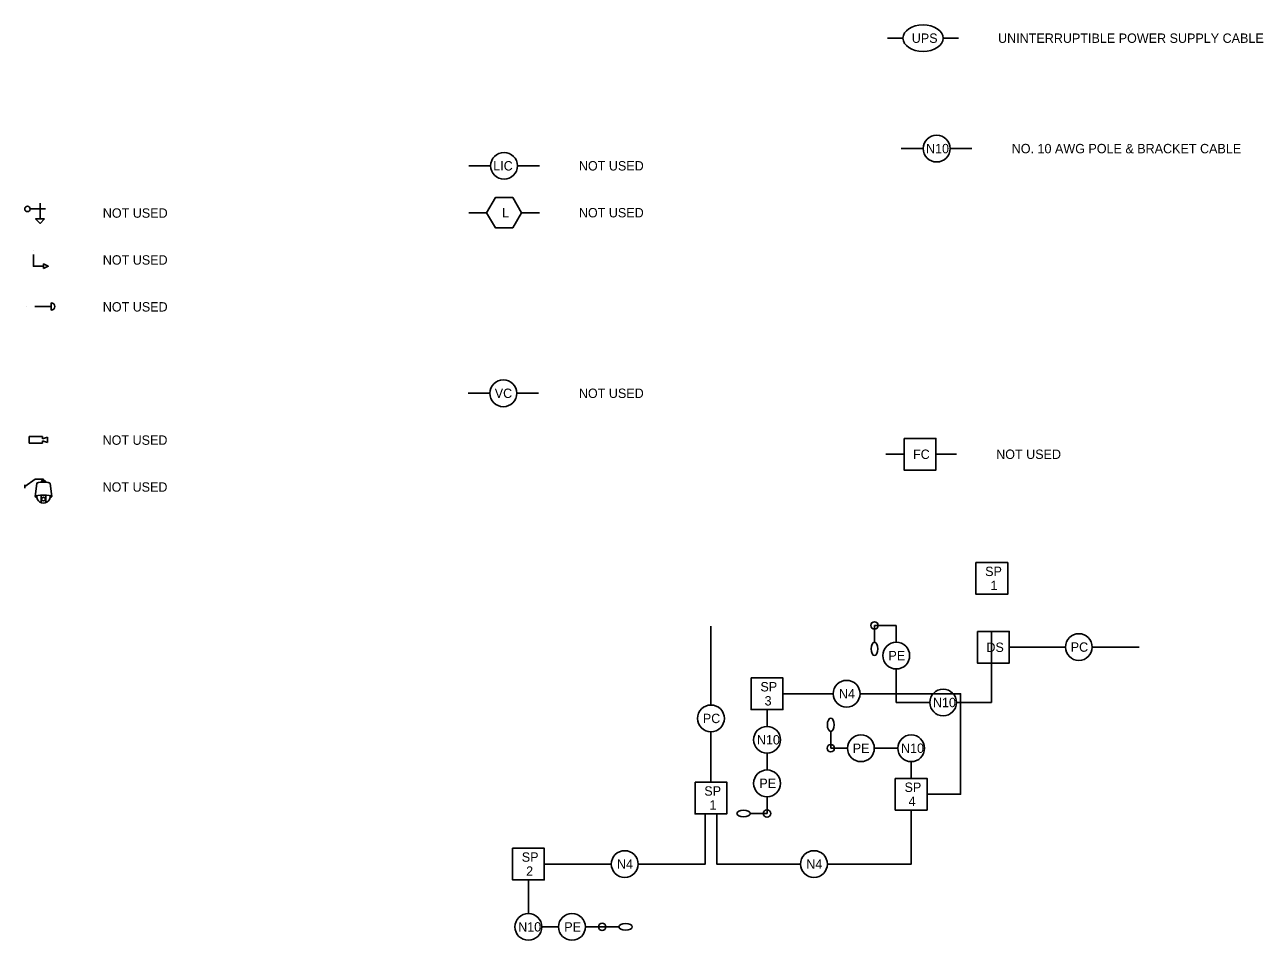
# Model space of a CAD drawing. Extents: x 32.6 to 95.8, y 11.4 to 49.5.
# Drawn here: x 55.45 to 73.93, y 11.38 to 25.04 of the extents above; entities that cross this region are included whole.
import ezdxf

# ---------------------------------------------------------------- set-up
doc = ezdxf.new("R2010")
doc.units = 0
for name, color, linetype in [('LT_P_Luminaires', 7, 'Continuous'), ('SG_P_Detection', 7, 'Continuous'), ('SG_P_Heads', 7, 'Continuous'), ('SG_P_Text', 7, 'Continuous'), ('SH_Data', 7, 'Continuous'), ('SH_Text', 7, 'Continuous')]:
    doc.layers.add(name, color=color, linetype=linetype)

msp = doc.modelspace()

# ---------------------------------------------------------------- linework, layer by layer
at = {"layer": 'LT_P_Luminaires'}
for p, q in [((68.129, 16.078), (68.129, 15.828)), ((67.477, 14.245), (67.477, 14.495)), ((66.527, 13.271), (66.277, 13.271)), ((64.067, 11.579), (64.317, 11.579))]:
    msp.add_line(p, q, dxfattribs=at)
for centre in [(68.129, 16.078), (67.477, 14.245), (66.527, 13.271), (64.067, 11.579)]:
    msp.add_circle(centre, 0.055, dxfattribs=at)
for centre, major_axis in [((68.129, 15.728), (0, -0.1)), ((67.477, 14.595), (0, 0.1)), ((66.177, 13.271), (-0.1, 0)), ((64.417, 11.579), (0.1, 0))]:
    msp.add_ellipse(centre, major_axis=major_axis, ratio=0.5, dxfattribs=at)
at = {"layer": 'SG_P_Detection'}
for p, q in [((55.846, 20.894), (55.846, 20.782)), ((55.486, 20.838), (55.486, 20.838)), ((55.606, 20.838), (55.846, 20.838)), ((55.52, 18.9), (55.72, 18.9)), ((55.52, 18.8), (55.52, 18.9)), ((55.72, 18.9), (55.72, 18.865)), ((55.72, 18.865), (55.795, 18.89)), ((55.795, 18.89), (55.795, 18.81)), ((55.72, 18.8), (55.52, 18.8)), ((55.795, 18.81), (55.72, 18.835)), ((55.72, 18.835), (55.72, 18.8)), ((55.454, 18.125), (55.454, 18.175)), ((55.632, 18.198), (55.607, 18.002)), ((55.732, 18.262), (55.732, 18.237)), ((55.832, 18.198), (55.857, 18.002)), ((55.697, 18.022), (55.697, 17.909)), ((55.767, 18.022), (55.767, 17.909))]:
    msp.add_line(p, q, dxfattribs=at)
for points in [[(55.732, 18.262), (55.607, 18.262), (55.454, 18.15)], [(55.707, 18.217), (55.707, 18.237), (55.757, 18.237), (55.757, 18.217)]]:
    msp.add_lwpolyline(points, dxfattribs=at)
msp.add_circle((55.732, 17.964), 0.0273, dxfattribs=at)
for centre, radius, start, end in [((55.846, 20.838), 0.056, 270.0002, 89.9998), ((55.732, 18.002), 0.1, 173.0175, 6.9825)]:
    msp.add_arc(centre, radius, start, end, dxfattribs=at)
for centre, major_axis, ratio, start_param, end_param in [((55.732, 18.198), (0.1, 0), 0.2, 0, 3.141593), ((55.732, 18.002), (0.125, 0), 0.16, 5.62986, 10.078104)]:
    msp.add_ellipse(centre, major_axis=major_axis, ratio=ratio, start_param=start_param, end_param=end_param, dxfattribs=at)
at = {"layer": 'SG_P_Heads'}
for p, q in [((55.683, 22.38), (55.683, 22.145)), ((55.534, 22.294), (55.764, 22.294)), ((55.584, 21.673), (55.584, 21.673))]:
    msp.add_line(p, q, dxfattribs=at)
for points in [[(55.75, 22.145), (55.683, 22.078), (55.616, 22.145)], [(55.734, 21.403), (55.734, 21.473), (55.804, 21.438)]]:
    msp.add_lwpolyline(points, close=True, dxfattribs=at)
msp.add_lwpolyline([(55.584, 21.613), (55.584, 21.438), (55.734, 21.438)], dxfattribs=at)
msp.add_circle((55.494, 22.294), 0.04, dxfattribs=at)
at = {"layer": 'SG_P_Text'}
for p, q in [((68.554, 24.843), (68.326, 24.843)), ((69.381, 24.843), (69.154, 24.843)), ((68.857, 23.195), (68.53, 23.195)), ((69.584, 23.195), (69.257, 23.195)), ((62.404, 22.938), (62.077, 22.938)), ((63.131, 22.938), (62.804, 22.938)), ((62.344, 22.238), (62.077, 22.238)), ((63.131, 22.238), (62.864, 22.238)), ((62.393, 19.543), (62.066, 19.543)), ((63.12, 19.543), (62.793, 19.543)), ((68.572, 18.633), (68.298, 18.633)), ((69.352, 18.633), (69.046, 18.633))]:
    msp.add_line(p, q, dxfattribs=at)
for points in [[(62.864, 22.238), (62.734, 22.463), (62.474, 22.463), (62.344, 22.238), (62.474, 22.013), (62.734, 22.013)], [(68.572, 18.87), (69.046, 18.87), (69.046, 18.396), (68.572, 18.396)], [(69.644, 17.017), (70.117, 17.017), (70.117, 16.543), (69.644, 16.543)], [(69.666, 15.989), (70.14, 15.989), (70.14, 15.515), (69.666, 15.515)], [(66.29, 15.295), (66.764, 15.295), (66.764, 14.821), (66.29, 14.821)], [(65.454, 13.74), (65.927, 13.74), (65.927, 13.266), (65.454, 13.266)], [(68.44, 13.795), (68.914, 13.795), (68.914, 13.321), (68.44, 13.321)], [(62.73, 12.753), (63.204, 12.753), (63.204, 12.279), (62.73, 12.279)]]:
    msp.add_lwpolyline(points, close=True, dxfattribs=at)
for centre in [(69.057, 23.195), (62.604, 22.938), (62.593, 19.543), (71.178, 15.755), (68.454, 15.628), (67.714, 15.058), (69.154, 14.928), (65.69, 14.69), (66.527, 14.371), (67.927, 14.245), (68.677, 14.245), (66.527, 13.721), (64.404, 12.516), (67.227, 12.516), (62.967, 11.579), (63.617, 11.579)]:
    msp.add_circle(centre, 0.2, dxfattribs=at)
msp.add_ellipse((68.854, 24.843), major_axis=(0.3, 0), ratio=0.666667, dxfattribs=at)
at = {"layer": 'SH_Data'}
for p, q in [((68.129, 16.078), (68.454, 16.078)), ((68.454, 15.828), (68.454, 16.078)), ((65.69, 16.066), (65.69, 14.89)), ((69.876, 15.992), (69.876, 14.928)), ((70.978, 15.755), (70.14, 15.755)), ((72.078, 15.755), (71.378, 15.755)), ((68.454, 14.928), (68.454, 15.428)), ((67.514, 15.058), (66.764, 15.058)), ((66.527, 14.821), (66.527, 14.571)), ((68.954, 14.928), (68.454, 14.928)), ((69.876, 14.928), (69.354, 14.928)), ((65.69, 14.49), (65.69, 13.74)), ((67.727, 14.245), (67.477, 14.245)), ((68.477, 14.245), (68.127, 14.245)), ((66.527, 14.171), (66.527, 13.921)), ((68.677, 13.795), (68.677, 14.045)), ((66.527, 13.521), (66.527, 13.271)), ((64.204, 12.516), (63.204, 12.516)), ((62.967, 12.279), (62.967, 11.779)), ((63.167, 11.579), (63.417, 11.579)), ((63.817, 11.579), (64.067, 11.579))]:
    msp.add_line(p, q, dxfattribs=at)
for points in [[(68.914, 13.558), (69.414, 13.558), (69.414, 15.058), (67.914, 15.058)], [(67.427, 12.516), (68.677, 12.516), (68.677, 13.321)], [(65.604, 13.266), (65.604, 12.516), (64.604, 12.516)], [(65.777, 13.266), (65.777, 12.516), (67.027, 12.516)]]:
    msp.add_lwpolyline(points, dxfattribs=at)

# ---------------------------------------------------------------- texts
at = {"layer": 'SG_P_Text'}
for s, p in [('UPS', (68.686, 24.773)), ('N10', (68.898, 23.125)), ('LIC', (62.442, 22.868)), ('VC', (62.465, 19.473)), ('FC', (68.705, 18.563)), ('SP', (69.781, 16.815)), ('1', (69.86, 16.605)), ('DS', (69.799, 15.682)), ('SP', (66.428, 15.093)), ('3', (66.49, 14.883)), ('SP', (65.591, 13.537)), ('SP', (68.578, 13.593)), ('4', (68.638, 13.383)), ('1', (65.669, 13.329)), ('SP', (62.868, 12.551)), ('2', (62.933, 12.341))]:
    msp.add_text(s, height=0.14, dxfattribs=at).set_placement(p)
for s, p in [('L', (62.573, 22.168)), ('PC', (71.057, 15.685)), ('PE', (68.338, 15.558)), ('N4', (67.599, 14.988)), ('N10', (69.001, 14.858)), ('PC', (65.569, 14.62)), ('N10', (66.375, 14.301)), ('PE', (67.805, 14.175)), ('N10', (68.525, 14.175)), ('PE', (66.412, 13.651)), ('N4', (64.288, 12.446)), ('N4', (67.112, 12.446)), ('N10', (62.814, 11.509)), ('PE', (63.502, 11.509))]:
    msp.add_text(s, height=0.14, rotation=360, dxfattribs=at).set_placement(p)
at = {"layer": 'SH_Text'}
for s, p in [('UNINTERRUPTIBLE POWER SUPPLY CABLE', (69.973, 24.773)), ('NO. 10 AWG POLE & BRACKET CABLE', (70.177, 23.125)), ('NOT USED', (63.72, 22.868)), ('NOT USED', (56.618, 22.163)), ('NOT USED', (63.72, 22.168)), ('NOT USED', (56.618, 21.463)), ('NOT USED', (56.618, 20.763)), ('NOT USED', (63.72, 19.473)), ('NOT USED', (56.615, 18.774)), ('NOT USED', (69.945, 18.563)), ('NOT USED', (56.615, 18.074))]:
    msp.add_text(s, height=0.14, dxfattribs=at).set_placement(p)

doc.saveas('drawing.dxf')
